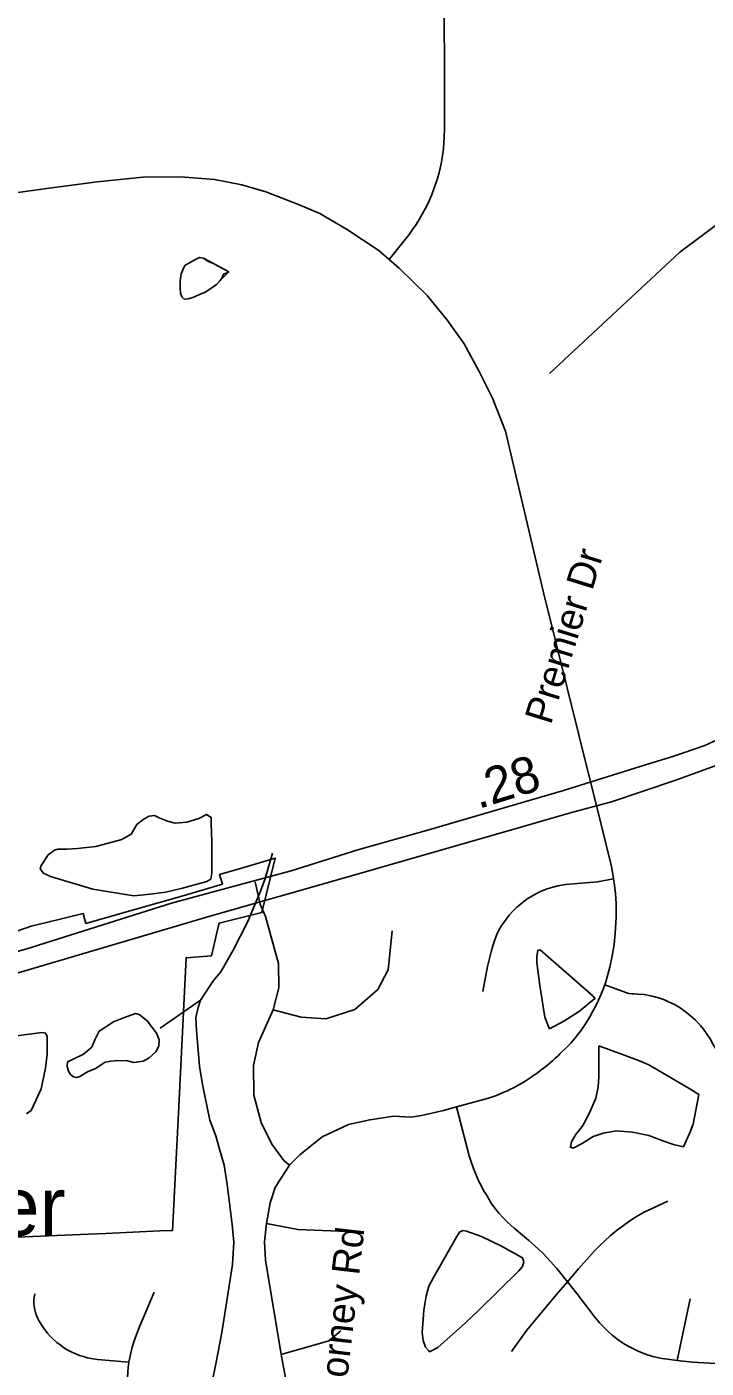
# Model space of a CAD drawing. Extents: x 1662474 to 1856135, y 779280 to 917889.
# Drawn here: x 1716872 to 1719194, y 830593 to 835176 of the extents above; entities that cross this region are included whole.
import ezdxf

# ---------------------------------------------------------------- set-up
doc = ezdxf.new("R2010")
doc.units = 0
for name, color, linetype in [('Exist Boundary Political City Limit New Hole', 7, 'Continuous'), ('Exist Civil Demographics Community Label', 7, 'Continuous'), ('Exist Hydrographic Misc Water Feature', 7, 'Continuous'), ('Exist Hydrographic Pond Under 1500 Sq Ft', 7, 'Continuous'), ('Exist Road Non-System Type 51', 7, 'Continuous'), ('Exist Road Non-System Type 51 Label', 7, 'Continuous'), ('Exist Road Secondary Mileage Tenths English Label', 7, 'Continuous'), ('Exist Road Secondary Type 51 Divided Attributed', 7, 'Continuous'), ('Map Preparation Boundary City Limit Buffer Line', 7, 'Continuous')]:
    doc.layers.add(name, color=color, linetype=linetype)

msp = doc.modelspace()

# ---------------------------------------------------------------- linework, layer by layer
at = {"layer": 'Exist Boundary Political City Limit New Hole'}
for points in [[(1716811.8, 831039), (1716947.6, 831045), (1717082.8, 831050.9), (1717142.1, 831053.5), (1717326.2, 831061.6), (1717368, 831063.4), (1717370, 831063.5), (1717391.1, 831463.9), (1717416.4, 831995.1), (1717503.9, 832002), (1717527.6, 832104.9), (1717529.6, 832113.5), (1717675.5, 832149.8), (1717721.5, 832335.7), (1717613.9, 832304), (1717530.6, 832279.4), (1717541.1, 832246.8), (1717402, 832206.1)], [(1717402, 832206.1), (1717173, 832140.9), (1717073.9, 832112.6), (1717064.1, 832146), (1716939.6, 832116.2), (1716886.4, 832103.4), (1716712.4, 832042.4)]]:
    msp.add_lwpolyline(points, dxfattribs=at)
at = {"layer": 'Exist Hydrographic Misc Water Feature'}
msp.add_line((1717328, 831755.2), (1717465.5, 831850.8), dxfattribs=at)
for points in [[(1718658.3, 833992.2), (1719104.3, 834406.5), (1719566.4, 834751.6), (1719758.3, 834839.6)], [(1717562.2, 834339.4), (1717524.2, 834359.9), (1717510.3, 834367.6), (1717494.1, 834373.6), (1717476.4, 834386.3), (1717462.3, 834388.2), (1717446.3, 834380.4), (1717428.3, 834370.1), (1717412.3, 834360.5), (1717406, 834348.4), (1717400, 834332.1), (1717395.8, 834308.4), (1717395.8, 834284.5), (1717397.6, 834266.4), (1717401.6, 834254), (1717409.8, 834245.7), (1717423.7, 834246.3), (1717439.6, 834251.6), (1717459.9, 834260.2), (1717481.8, 834269.7), (1717498, 834280), (1717520, 834296), (1717532, 834308.1), (1717538.2, 834317.8), (1717544.1, 834331.6), (1717555.5, 834335.4), (1717559, 834337), (1717562.2, 834339.4)], [(1717562.2, 834339.4), (1717476.4, 834386.3), (1717462.3, 834388.2), (1717446.3, 834380.4), (1717428.3, 834370.1), (1717412.3, 834360.5), (1717406, 834348.4), (1717400, 834332.1), (1717395.8, 834308.4), (1717395.8, 834284.5), (1717397.6, 834266.4), (1717401.6, 834254), (1717409.8, 834245.7), (1717423.7, 834246.3), (1717439.6, 834251.6), (1717459.9, 834260.2), (1717481.8, 834269.7), (1717498, 834280), (1717520, 834296), (1717532, 834308.1), (1717562.2, 834339.4)], [(1717465.5, 831850.8), (1717510.7, 831917.2), (1717534.8, 831947.1), (1717577.5, 832020.9), (1717626.2, 832116.8), (1717670.8, 832222.5), (1717687.1, 832266.5), (1717712.2, 832352.1)], [(1717476.2, 830245.5), (1717474.5, 830262), (1717474.5, 830292.3), (1717475.3, 830402.3), (1717496.1, 830502), (1717506.3, 830551.8), (1717516.6, 830601.7), (1717527, 830654), (1717539.3, 830721.9), (1717574.8, 830947.6), (1717579.3, 831023.8), (1717573.6, 831083.9), (1717556.4, 831220.5), (1717546.8, 831286.3), (1717531.2, 831340.8), (1717517.6, 831387), (1717497.7, 831440.7), (1717472.4, 831562.7), (1717462.8, 831625.3), (1717457.2, 831679.5), (1717451.7, 831746.9), (1717449.8, 831791.3), (1717458.1, 831825.6), (1717465.5, 831850.8)], [(1719142.4, 831407.6), (1719149.6, 831426.2), (1719168.7, 831528.4), (1719138.1, 831547.9), (1718998.2, 831628.8), (1718966.3, 831642.5), (1718908.4, 831665), (1718827.1, 831694.2)]]:
    msp.add_lwpolyline(points, dxfattribs=at)
at = {"layer": 'Exist Hydrographic Pond Under 1500 Sq Ft'}
for points in [[(1717501.5, 832264), (1717504.4, 832283.8), (1717504.9, 832320.5), (1717504.9, 832392.4), (1717502.6, 832452.5), (1717502.5, 832474.7), (1717486.1, 832484.9), (1717460.4, 832471.2), (1717418.6, 832458.3), (1717378.7, 832455.4), (1717352.6, 832461.6), (1717325, 832472.9), (1717308.5, 832481.1), (1717290.4, 832479), (1717272.6, 832469.4), (1717248.3, 832451.1), (1717229.1, 832417.5), (1717197, 832399.3), (1717107.4, 832375.3), (1717045.8, 832368.4), (1717009.8, 832366.6), (1716978.2, 832366.7), (1716967, 832363.3), (1716945.5, 832346.5), (1716921.4, 832310), (1716917.5, 832298.6), (1716929.3, 832284.4), (1716953.3, 832272.4), (1717097.2, 832229.7), (1717237.7, 832207.4), (1717294.1, 832212.4), (1717347.3, 832219.4), (1717403.9, 832233.1), (1717487.8, 832255.4), (1717501.5, 832264)], [(1718758, 831810), (1718707.4, 831778.2), (1718659, 831752.9), (1718653.1, 831766.2), (1718643.1, 831792.6), (1718625.8, 831900.5), (1718616, 831978.6), (1718616, 832000.8), (1718618.3, 832020.4), (1718626.4, 832022.7), (1718807.7, 831863.9), (1718813.8, 831855.6), (1718761.5, 831812.4), (1718758, 831810)], [(1717315.7, 831737.5), (1717283.7, 831780.1), (1717256, 831801.5), (1717243.2, 831804.7), (1717202.6, 831789.7), (1717168.5, 831775.9), (1717119.4, 831743.9), (1717104.5, 831715.1), (1717093.8, 831689.5), (1717066.1, 831666), (1717027.7, 831647.9), (1717011.6, 831639.4), (1717009.5, 831623.4), (1717014.8, 831607.4), (1717021.3, 831596.7), (1717031.9, 831588.2), (1717041.5, 831586), (1717053.3, 831589.2), (1717079.9, 831605.2), (1717106.6, 831617), (1717139.7, 831638.3), (1717158.9, 831641.5), (1717171.7, 831642.6), (1717211.2, 831644.7), (1717237.8, 831637.2), (1717269.9, 831641.5), (1717290.1, 831653.2), (1717312.5, 831673.5), (1717323.2, 831692.7), (1717324.3, 831715.1), (1717315.7, 831737.5)], [(1716870.6, 831461.6), (1716886.9, 831473.5), (1716902.9, 831507.6), (1716921.1, 831547.5), (1716935.5, 831617.8), (1716941.8, 831665.3), (1716942, 831693.1), (1716942, 831727.6), (1716936.1, 831737.6), (1716924, 831739.5), (1716799.9, 831724)], [(1718827.1, 831694.2), (1718827.1, 831618.2), (1718826.9, 831587.8), (1718824.9, 831554.3), (1718816.6, 831515.8), (1718800.5, 831475.9), (1718782.2, 831437.7), (1718770.1, 831418.3), (1718748, 831390.1), (1718733.9, 831366.6), (1718730, 831347.8), (1718740, 831344.2), (1718769.9, 831360.1), (1718808, 831383.9), (1718842.1, 831395.5), (1718888.3, 831403.7), (1718942.3, 831399.2), (1718998.5, 831387.4), (1719046.4, 831369.2), (1719082.1, 831357), (1719116.3, 831348.9), (1719140.5, 831402.6), (1719149.6, 831426.2)], [(1718350.6, 831057.2), (1718338.6, 831037), (1718279.9, 830934.7), (1718262, 830903.1), (1718245.7, 830873.1), (1718237.5, 830838.7), (1718229.4, 830791.3), (1718223.1, 830715.1), (1718226.7, 830687.2), (1718234.7, 830664.8), (1718244.8, 830653.2), (1718248.8, 830649), (1718276.8, 830663.2), (1718371.5, 830748.2), (1718417.4, 830790.8), (1718554.1, 830925.9), (1718566.4, 830940.4), (1718570.5, 830955.9), (1718566.5, 830969.9), (1718494.5, 831009.9), (1718426.5, 831042.5), (1718374.5, 831060.8), (1718362.6, 831062.7), (1718350.6, 831057.2)]]:
    msp.add_lwpolyline(points, dxfattribs=at)
at = {"layer": 'Exist Road Non-System Type 51'}
for p, q in [((1718800.6, 832591.7), (1718818.5, 832520.1)), ((1717670.2, 832178.6), (1717652.9, 832254.7)), ((1719095.4, 830619.4), (1719139.5, 830829.9))]:
    msp.add_line(p, q, dxfattribs=at)
for points in [[(1718110.4, 834380.9), (1718178.9, 834467), (1718190.9, 834483.5), (1718202.5, 834500.6), (1718213.5, 834517.9), (1718224, 834535.7), (1718233.8, 834554), (1718243.1, 834572), (1718255.2, 834600.1), (1718262.6, 834619.5), (1718269.6, 834638.9), (1718275.8, 834658.4), (1718281.2, 834678.2), (1718288.1, 834708.5), (1718292.1, 834728.4), (1718295.9, 834758.9), (1718298, 834779.4), (1718299.1, 834799.5), (1718299.6, 834829.2), (1718298.4, 835415.5), (1718296.5, 835497.2), (1718301.1, 835570.4), (1718304.1, 835591.2), (1718315.4, 835657.9)], [(1715545.4, 834570.9), (1715670, 834566.2), (1715844, 834553.1), (1716009.6, 834542.1), (1716160, 834537.6), (1716303.9, 834544.4), (1716460.6, 834559.7), (1716652.1, 834583.5), (1716948.1, 834624.5), (1717112, 834646.8), (1717268.4, 834663.1), (1717397.5, 834664.1), (1717513.1, 834654.4), (1717607.5, 834636), (1717689.6, 834611.9), (1717800.9, 834568.9), (1717873.6, 834537.9), (1717964.8, 834484.6), (1718074.9, 834411.6), (1718110.4, 834380.9)], [(1718110.4, 834380.9), (1718144.5, 834351.4), (1718241.4, 834256.8), (1718309.6, 834172.5), (1718366.6, 834093), (1718416.9, 834000.7), (1718463.6, 833907.9), (1718508.1, 833794.1), (1718636.9, 833247.9), (1718800.6, 832591.7)], [(1718877.4, 832264.9), (1718874.6, 832288), (1718869.4, 832311.4), (1718818.5, 832520.1)], [(1718430.4, 831880.4), (1718447.1, 831965.5), (1718458.9, 832015.6), (1718464.6, 832035.6), (1718472.8, 832060.2), (1718479.1, 832075.2), (1718486, 832089.4), (1718493.9, 832102.8), (1718502.2, 832116.2), (1718511.4, 832127.9), (1718520.9, 832141.1), (1718535.1, 832155.8), (1718546.1, 832167.4), (1718557.9, 832177), (1718569.6, 832186.8), (1718582.6, 832196.4), (1718600.1, 832207.2), (1718614.1, 832215.1), (1718628.2, 832221.1), (1718647.4, 832229.8), (1718662.4, 832234.2), (1718687.2, 832241.1), (1718713, 832245.5), (1718823.2, 832254.2), (1718877.4, 832264.9)], [(1718847.6, 831903), (1718849.8, 831909.6), (1718854.5, 831925.6), (1718865.2, 831963.4), (1718873.1, 832001.4), (1718879.9, 832040.9), (1718883.6, 832079.7), (1718886.5, 832132.4), (1718886.8, 832156), (1718886.2, 832180.2), (1718883.9, 832215.9), (1718879.4, 832251.6), (1718877.4, 832264.9)], [(1717714.4, 831816.9), (1717733.8, 831892), (1717731.9, 831975.8), (1717688.1, 832136.6), (1717670.2, 832178.6)], [(1717714.4, 831816.9), (1717809.9, 831791.8), (1717894.4, 831786.8), (1717993.4, 831818.2), (1718072.4, 831887), (1718107.8, 831953.7), (1718121.4, 832087.8)], [(1718341.4, 831485.7), (1718424.6, 831508.5), (1718449.9, 831515.4), (1718478.1, 831525.1), (1718503.2, 831535.6), (1718514.6, 831540.9), (1718524.9, 831545.9), (1718535.6, 831551.1), (1718545.9, 831556.4), (1718556, 831561.9), (1718566, 831568.4), (1718575.9, 831573.6), (1718586, 831580.2), (1718595.9, 831587), (1718605.6, 831593.6), (1718615.1, 831599.9), (1718624.6, 831607.2), (1718633.8, 831614.4), (1718643.1, 831621.1), (1718652.1, 831628.2), (1718661, 831636.4), (1718669.9, 831643.7), (1718678.6, 831651.9), (1718687, 831659.2), (1718695.6, 831667.9), (1718719.9, 831691.6), (1718731.9, 831703.5), (1718744, 831717.8), (1718754.8, 831731.4), (1718765.8, 831745.9), (1718783.6, 831772.6), (1718796.8, 831793.6), (1718806.9, 831812.5), (1718816.9, 831831), (1718825.9, 831849.8), (1718834, 831868.6), (1718841.9, 831887.8), (1718847.6, 831903)], [(1718847.6, 831903), (1718920.1, 831876.5), (1718929.8, 831873.6), (1718941.1, 831871.8), (1718948.1, 831871.5), (1718960.8, 831871), (1718982.9, 831869.2), (1719009.9, 831864.2), (1719030.9, 831858.4), (1719051.6, 831851.4), (1719066, 831844.5), (1719085.9, 831835.4), (1719104.9, 831823.9), (1719123, 831811.9), (1719140, 831798.4), (1719156.4, 831783.6), (1719174.9, 831763.4), (1719185.1, 831751.1), (1719198.2, 831732.9), (1719209.9, 831714.9), (1719217.6, 831699.6), (1719238.6, 831667.1)], [(1717770.4, 831286.5), (1717751.1, 831302.8), (1717709.9, 831358.2), (1717673.6, 831432.2), (1717648.4, 831525.6), (1717647.4, 831627.4), (1717664.1, 831706.2), (1717714.4, 831816.9)], [(1717770.4, 831286.5), (1717805.6, 831322.2), (1717881.8, 831382.9), (1717971.2, 831425.1), (1718044.2, 831441.9), (1718126.6, 831453.4), (1718184.6, 831450.5), (1718215.9, 831455.5), (1718247.1, 831461.9), (1718271.5, 831467.1), (1718295.9, 831473.4), (1718341.4, 831485.7)], [(1718341.4, 831485.7), (1718384.1, 831318.9), (1718389.6, 831300.9), (1718398.4, 831275.5), (1718408.9, 831249.8), (1718416.4, 831232.9), (1718425.1, 831216.9), (1718433.5, 831200.4), (1718442.9, 831184.7), (1718459.1, 831156.9), (1718472.1, 831139.8), (1718486, 831122.8), (1718500.1, 831106.2), (1718514.9, 831091.2), (1718537.4, 831070.8), (1718588.4, 831028.8), (1718607.8, 831011.7), (1718635.6, 830985.7), (1718662.1, 830957.6), (1718683.6, 830932.9), (1718720.4, 830887.9)], [(1717691, 831087), (1717703.6, 831157.7), (1717721.4, 831210.7), (1717740.1, 831241.1), (1717770.4, 831286.5)], [(1718720.4, 830887.9), (1718757.4, 830931.9), (1718795.1, 830974.9), (1718812.1, 830993.8), (1718829.5, 831010.9), (1718847.6, 831028.2), (1718866.5, 831044.9), (1718886.2, 831061.6), (1718916.1, 831083.7), (1718936.6, 831098.6), (1718957.9, 831112.2), (1718982.6, 831126.4), (1719063.4, 831163.4)], [(1717741.1, 830640), (1717687.6, 830962.4), (1717684.4, 831024.9), (1717691, 831087)], [(1717691, 831087), (1717798.6, 831066.7), (1717966.9, 831059.4)], [(1717221.1, 830613.5), (1717226.4, 830639.8), (1717232.4, 830664.2), (1717238.2, 830683.1), (1717247.4, 830708.2), (1717258.1, 830737.2), (1717270, 830764.2), (1717306.9, 830852.7)], [(1718529, 830649.8), (1718581.8, 830723), (1718682.6, 830844), (1718720.4, 830887.9)], [(1718720.4, 830887.9), (1718752.6, 830848.2), (1718814, 830767.6), (1718830.9, 830746.6), (1718844.2, 830732.7), (1718858.4, 830718.8), (1718873.4, 830705.7), (1718893.9, 830690.2), (1718915.6, 830675.2), (1718938.9, 830661.9), (1718962.4, 830650.9), (1718986.5, 830641.1), (1719011.9, 830633.2), (1719037.1, 830626.9), (1719044.5, 830625.6), (1719095.4, 830619.4)], [(1716899.6, 830846.4), (1716897.6, 830835.6), (1716896.5, 830824), (1716896.2, 830814.6), (1716897, 830803.2), (1716899, 830792.5), (1716901.4, 830782.9), (1716904.9, 830773.1), (1716909.4, 830762.9), (1716914.8, 830753.2), (1716924.1, 830737.7), (1716931.6, 830726.7), (1716942.9, 830712.5), (1716951.9, 830702.5), (1716961.4, 830693.1), (1716974.6, 830680.7), (1716985.5, 830672.4), (1716996.5, 830664.8), (1717007.8, 830657.1), (1717028, 830646.9), (1717040.1, 830641.4), (1717052.4, 830636.4), (1717065.5, 830632.2), (1717078.4, 830628.5), (1717091.5, 830625.4), (1717113.8, 830622.4), (1717221.1, 830613.5)], [(1717741.1, 830640), (1717904.6, 830685.8), (1717945.2, 830720.9)], [(1717725.4, 830218.2), (1717744.5, 830248.4), (1717763.9, 830289.9), (1717777.1, 830333), (1717784.4, 830378.1), (1717785.4, 830400.7), (1717741.1, 830640)], [(1717161.1, 830158.7), (1717194.9, 830284.4), (1717198.9, 830303.4), (1717202.5, 830326.2), (1717205.4, 830358.2), (1717217.5, 830579.9), (1717218.2, 830594.7), (1717221.1, 830613.5)], [(1719095.4, 830619.4), (1719147.1, 830613.2), (1719500.9, 830592.9)]]:
    msp.add_lwpolyline(points, dxfattribs=at)
at = {"layer": 'Exist Road Secondary Type 51 Divided Attributed'}
for points in [[(1719302.9, 832774.8), (1719264.3, 832754.4), (1719189.9, 832720.8), (1719079.9, 832682.4), (1718987.1, 832654.3), (1718855.3, 832614), (1718706.2, 832566.3), (1718507.2, 832509), (1718245.7, 832431.9), (1718004.1, 832364.5), (1717775.2, 832292.4), (1717567.9, 832237), (1717367.1, 832181.3), (1716872.4, 832025.4), (1716579.7, 831944.6), (1716058.2, 831791.8), (1715769.4, 831707.5), (1715661.7, 831674.9), (1715469.6, 831615), (1715017.3, 831486.1)], [(1715033.7, 831443.2), (1715290.4, 831506), (1715685.7, 831609.1), (1716363, 831806.9), (1716710.8, 831905.5), (1717501.9, 832138.8), (1717966.5, 832270.5), (1718569, 832443.5), (1718734.2, 832491.7), (1718870.3, 832528.4), (1719086.7, 832600.4), (1719237.9, 832656.1), (1719333.3, 832698.6)]]:
    msp.add_lwpolyline(points, dxfattribs=at)
at = {"layer": 'Map Preparation Boundary City Limit Buffer Line'}
for points in [[(1716811.8, 831039), (1716947.6, 831045), (1717082.8, 831050.9), (1717142.1, 831053.5), (1717326.2, 831061.6), (1717368, 831063.4), (1717370, 831063.5), (1717391.1, 831463.9), (1717416.4, 831995.1), (1717503.9, 832002), (1717527.6, 832104.9), (1717529.6, 832113.5), (1717675.5, 832149.8), (1717721.5, 832335.7), (1717613.9, 832304), (1717530.6, 832279.4), (1717541.1, 832246.8), (1717402, 832206.1)], [(1717402, 832206.1), (1717173, 832140.9), (1717073.9, 832112.6), (1717064.1, 832146), (1716939.6, 832116.2), (1716886.4, 832103.4), (1716712.4, 832042.4)]]:
    msp.add_lwpolyline(points, dxfattribs=at)

# ---------------------------------------------------------------- texts
at = {"layer": 'Exist Civil Demographics Community Label'}
msp.add_text('Deep River', height=200, dxfattribs=at).set_placement((1715667.2, 831045.9))
at = {"layer": 'Exist Road Non-System Type 51 Label'}
for s, rotation, p in [('Premier Dr', 72.8641, (1718663.3, 832788.5)), ('Horney Rd', 83.5099, (1717957.6, 830466))]:
    msp.add_text(s, height=95, rotation=rotation, dxfattribs=at).set_placement(p)
at = {"layer": 'Exist Road Secondary Mileage Tenths English Label'}
msp.add_text('.28', height=125, rotation=17.3818, dxfattribs=at).set_placement((1718415.4, 832502.9))

doc.saveas('drawing.dxf')
